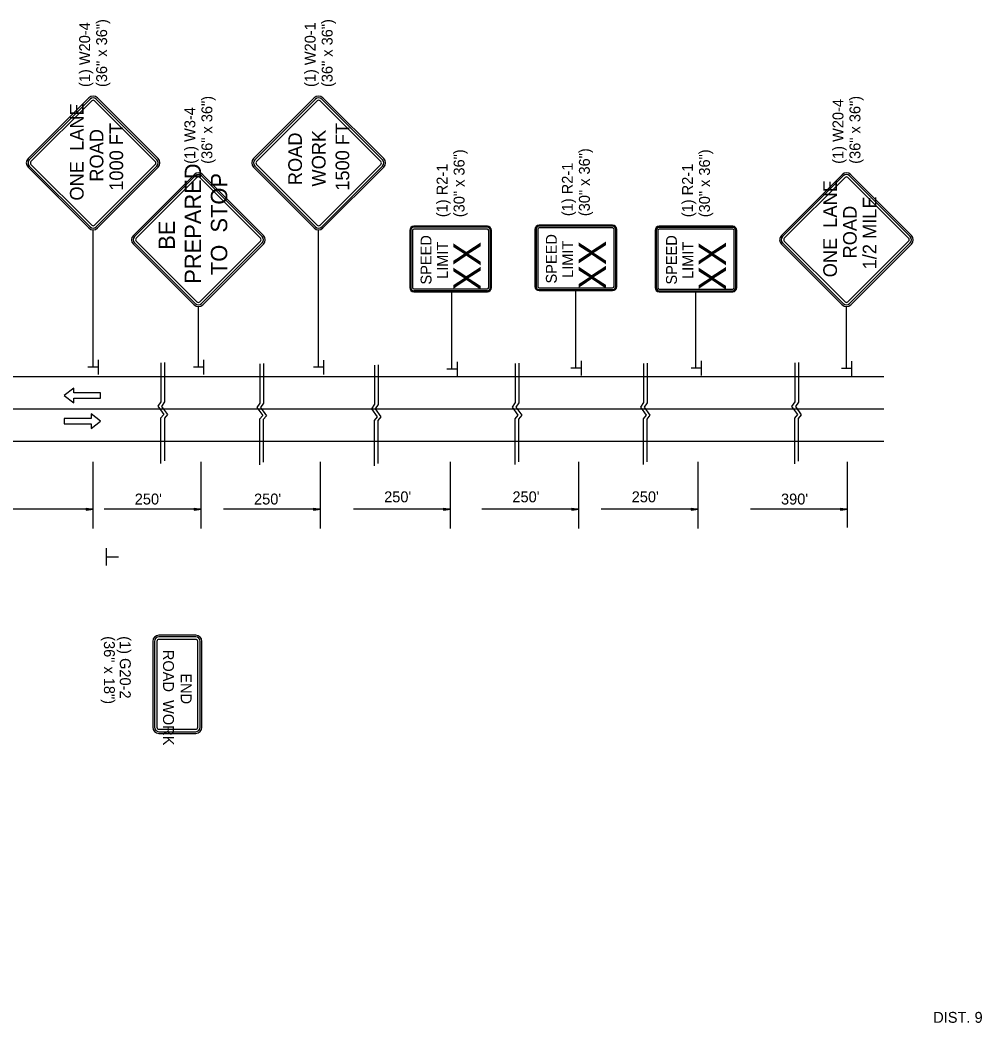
# Model space of a CAD drawing. Extents: x 1930579 to 1934718, y 596452 to 597844.
# Drawn here: x 1932620 to 1933150, y 596560 to 597112 of the extents above; entities that cross this region are included whole.
import ezdxf

# ---------------------------------------------------------------- set-up
doc = ezdxf.new("R2010")
doc.units = 0
for name, color, linetype in [('Default', 7, 'Continuous'), ('P_TC_Signs_Permanent', 7, 'Continuous'), ('P_TC_Signs_Temporary', 7, 'Continuous'), ('R_Annotation', 7, 'Continuous'), ('R_Striping', 7, 'Continuous')]:
    doc.layers.add(name, color=color, linetype=linetype)

msp = doc.modelspace()

# ---------------------------------------------------------------- linework, layer by layer
at = {"layer": 'Default'}
for p, q in [((1932663.23, 596924.51), (1932663.23, 596916.5)), ((1932721.33, 596924.51), (1932721.33, 596916.5)), ((1932787.34, 596924.41), (1932787.34, 596916.4)), ((1932860.88, 596923.37), (1932860.88, 596915.37)), ((1932929.09, 596923.95), (1932929.09, 596915.95)), ((1932995.19, 596923.9), (1932995.19, 596915.89)), ((1933078.02, 596923.73), (1933078.02, 596915.73)), ((1932663.11, 596920.53), (1932657.64, 596920.53)), ((1932721.21, 596920.53), (1932715.74, 596920.53)), ((1932787.22, 596920.43), (1932781.76, 596920.43)), ((1932860.76, 596919.39), (1932855.29, 596919.39)), ((1932928.98, 596919.97), (1932923.51, 596919.97)), ((1932995.08, 596919.92), (1932989.61, 596919.92)), ((1933077.9, 596919.75), (1933072.44, 596919.75)), ((1932378.86, 596915.33), (1932993.57, 596915.28)), ((1932993.57, 596915.28), (1933095.77, 596915.27)), ((1932378.14, 596897.54), (1933095.76, 596897.49)), ((1932378.64, 596879.75), (1932993.57, 596879.7)), ((1932993.57, 596879.7), (1933095.77, 596879.69)), ((1932660.61, 596831.69), (1932660.61, 596868.29)), ((1932720.06, 596831.69), (1932720.06, 596868.29)), ((1932785.71, 596831.69), (1932785.71, 596868.29)), ((1932857.31, 596831.69), (1932857.31, 596868.29)), ((1932927.92, 596831.69), (1932927.92, 596868.29)), ((1932993.57, 596831.69), (1932993.57, 596868.29)), ((1933075.76, 596832.26), (1933075.76, 596868.29)), ((1932660.61, 596842.28), (1932560.85, 596842.28)), ((1932656.77, 596842.85), (1932660.61, 596842.28)), ((1932656.77, 596842.85), (1932656.77, 596841.7)), ((1932656.77, 596842.76), (1932659.97, 596842.28)), ((1932656.77, 596842.66), (1932659.31, 596842.28)), ((1932656.77, 596842.56), (1932658.67, 596842.28)), ((1932656.77, 596842.46), (1932658.02, 596842.28)), ((1932656.77, 596842.37), (1932657.38, 596842.28)), ((1932656.77, 596841.7), (1932660.61, 596842.28)), ((1932656.77, 596842.09), (1932658.02, 596842.28)), ((1932656.77, 596841.89), (1932659.31, 596842.28)), ((1932656.77, 596841.8), (1932659.97, 596842.28)), ((1932656.77, 596841.99), (1932658.67, 596842.28)), ((1932656.77, 596842.19), (1932657.38, 596842.28)), ((1932720.06, 596842.28), (1932666.66, 596842.28)), ((1932716.22, 596842.85), (1932720.06, 596842.28)), ((1932716.22, 596842.85), (1932716.22, 596841.7)), ((1932716.22, 596842.76), (1932719.42, 596842.28)), ((1932716.22, 596842.66), (1932718.76, 596842.28)), ((1932716.22, 596842.56), (1932718.12, 596842.28)), ((1932716.22, 596842.46), (1932717.47, 596842.28)), ((1932716.22, 596842.37), (1932716.83, 596842.28)), ((1932716.22, 596841.7), (1932720.06, 596842.28)), ((1932716.22, 596842.09), (1932717.47, 596842.28)), ((1932716.22, 596841.89), (1932718.76, 596842.28)), ((1932716.22, 596841.8), (1932719.42, 596842.28)), ((1932716.22, 596841.99), (1932718.12, 596842.28)), ((1932716.22, 596842.19), (1932716.83, 596842.28)), ((1932785.71, 596842.28), (1932732.31, 596842.28)), ((1932781.88, 596842.85), (1932785.71, 596842.28)), ((1932781.88, 596842.85), (1932781.88, 596841.7)), ((1932781.88, 596842.76), (1932785.07, 596842.28)), ((1932781.88, 596842.66), (1932784.41, 596842.28)), ((1932781.88, 596842.56), (1932783.78, 596842.28)), ((1932781.88, 596842.46), (1932783.12, 596842.28)), ((1932781.88, 596842.37), (1932782.48, 596842.28)), ((1932781.88, 596841.7), (1932785.71, 596842.28)), ((1932781.88, 596842.09), (1932783.12, 596842.28)), ((1932781.88, 596841.89), (1932784.41, 596842.28)), ((1932781.88, 596841.8), (1932785.07, 596842.28)), ((1932781.88, 596841.99), (1932783.78, 596842.28)), ((1932781.88, 596842.19), (1932782.48, 596842.28)), ((1932857.31, 596842.28), (1932803.91, 596842.28)), ((1932853.47, 596842.85), (1932857.31, 596842.28)), ((1932853.47, 596842.85), (1932853.47, 596841.7)), ((1932853.47, 596842.76), (1932856.67, 596842.28)), ((1932853.47, 596842.66), (1932856.01, 596842.28)), ((1932853.47, 596842.56), (1932855.37, 596842.28)), ((1932853.47, 596842.46), (1932854.72, 596842.28)), ((1932853.47, 596842.37), (1932854.08, 596842.28)), ((1932853.47, 596841.7), (1932857.31, 596842.28)), ((1932853.47, 596842.09), (1932854.72, 596842.28)), ((1932853.47, 596841.89), (1932856.01, 596842.28)), ((1932853.47, 596841.8), (1932856.67, 596842.28)), ((1932853.47, 596841.99), (1932855.37, 596842.28)), ((1932853.47, 596842.19), (1932854.08, 596842.28)), ((1932927.92, 596842.28), (1932874.52, 596842.28)), ((1932924.08, 596842.85), (1932927.92, 596842.28)), ((1932924.08, 596842.85), (1932924.08, 596841.7)), ((1932924.08, 596842.76), (1932927.28, 596842.28)), ((1932924.08, 596842.66), (1932926.62, 596842.28)), ((1932924.08, 596842.56), (1932925.98, 596842.28)), ((1932924.08, 596842.46), (1932925.33, 596842.28)), ((1932924.08, 596842.37), (1932924.69, 596842.28)), ((1932924.08, 596841.7), (1932927.92, 596842.28)), ((1932924.08, 596842.09), (1932925.33, 596842.28)), ((1932924.08, 596841.89), (1932926.62, 596842.28)), ((1932924.08, 596841.8), (1932927.28, 596842.28)), ((1932924.08, 596841.99), (1932925.98, 596842.28)), ((1932924.08, 596842.19), (1932924.69, 596842.28)), ((1932993.57, 596842.28), (1932940.17, 596842.28)), ((1932989.73, 596842.85), (1932993.57, 596842.28)), ((1932989.73, 596842.85), (1932989.73, 596841.7)), ((1932989.73, 596842.76), (1932992.93, 596842.28)), ((1932989.73, 596842.66), (1932992.27, 596842.28)), ((1932989.73, 596842.56), (1932991.63, 596842.28)), ((1932989.73, 596842.46), (1932990.98, 596842.28)), ((1932989.73, 596842.37), (1932990.34, 596842.28)), ((1932989.73, 596841.7), (1932993.57, 596842.28)), ((1932989.73, 596842.09), (1932990.98, 596842.28)), ((1932989.73, 596841.89), (1932992.27, 596842.28)), ((1932989.73, 596841.8), (1932992.93, 596842.28)), ((1932989.73, 596841.99), (1932991.63, 596842.28)), ((1932989.73, 596842.19), (1932990.34, 596842.28)), ((1933075.76, 596842.28), (1933022.35, 596842.28)), ((1933071.92, 596842.85), (1933075.76, 596842.28)), ((1933071.92, 596842.85), (1933071.92, 596841.7)), ((1933071.92, 596842.76), (1933075.12, 596842.28)), ((1933071.92, 596842.66), (1933074.46, 596842.28)), ((1933071.92, 596842.56), (1933073.82, 596842.28)), ((1933071.92, 596842.46), (1933073.17, 596842.28)), ((1933071.92, 596842.37), (1933072.53, 596842.28)), ((1933071.92, 596841.7), (1933075.76, 596842.28)), ((1933071.92, 596842.09), (1933073.17, 596842.28)), ((1933071.92, 596841.89), (1933074.46, 596842.28)), ((1933071.92, 596841.8), (1933075.12, 596842.28)), ((1933071.92, 596841.99), (1933073.82, 596842.28)), ((1933071.92, 596842.19), (1933072.53, 596842.28)), ((1932667.87, 596811.37), (1932667.87, 596820.86)), ((1932668.01, 596816.09), (1932674.49, 596816.09))]:
    msp.add_line(p, q, dxfattribs=at)
for points in [[(1932697.84, 596922.91), (1932697.84, 596901.39), (1932696.18, 596898.92), (1932699.42, 596894.49), (1932697.71, 596892.44), (1932697.71, 596867.41)], [(1932699.89, 596923.11), (1932699.89, 596901.3), (1932698.23, 596898.83), (1932701.46, 596894.4), (1932699.76, 596892.36), (1932699.76, 596868.85)], [(1932754.35, 596922.46), (1932754.35, 596900.66), (1932752.69, 596898.18), (1932755.93, 596893.76), (1932754.22, 596891.71), (1932754.22, 596868.21)], [(1932892.79, 596922.48), (1932892.79, 596900.96), (1932891.13, 596898.49), (1932894.36, 596894.06), (1932892.66, 596892.01), (1932892.65, 596866.98)], [(1932894.83, 596922.67), (1932894.83, 596900.87), (1932893.17, 596898.4), (1932896.41, 596893.97), (1932894.7, 596891.92), (1932894.7, 596868.42)], [(1932963.4, 596922.48), (1932963.4, 596900.96), (1932961.73, 596898.49), (1932964.97, 596894.06), (1932963.27, 596892.01), (1932963.26, 596866.98)], [(1932965.44, 596922.67), (1932965.44, 596900.87), (1932963.78, 596898.4), (1932967.02, 596893.97), (1932965.31, 596891.92), (1932965.31, 596868.42)], [(1933046.67, 596922.82), (1933046.67, 596901.3), (1933045, 596898.83), (1933048.24, 596894.4), (1933046.54, 596892.35), (1933046.53, 596867.32)], [(1933048.71, 596923.02), (1933048.71, 596901.21), (1933047.05, 596898.74), (1933050.29, 596894.31), (1933048.58, 596892.27), (1933048.58, 596868.76)], [(1932752.31, 596922.26), (1932752.31, 596900.74), (1932750.64, 596898.27), (1932753.88, 596893.84), (1932752.18, 596891.8), (1932752.17, 596866.77)], [(1932815.35, 596921.59), (1932815.35, 596900.07), (1932813.68, 596897.6), (1932816.92, 596893.17), (1932815.22, 596891.12), (1932815.21, 596866.1)], [(1932817.39, 596921.79), (1932817.39, 596899.99), (1932815.73, 596897.51), (1932818.97, 596893.08), (1932817.26, 596891.04), (1932817.26, 596867.54)]]:
    msp.add_lwpolyline(points, dxfattribs=at)
at = {"layer": 'P_TC_Signs_Permanent'}
for p, q in [((1932716.09, 597026.42), (1932682.68, 596993.01)), ((1932716.75, 597025.75), (1932683.34, 596992.34)), ((1932717.68, 597024.82), (1932684.27, 596991.41)), ((1932752.68, 596991.41), (1932719.27, 597024.82)), ((1932753.61, 596992.34), (1932720.2, 597025.75)), ((1932754.27, 596993.01), (1932720.86, 597026.42)), ((1932834.78, 596995.76), (1932834.78, 596964.26)), ((1932835.34, 596995.76), (1932835.34, 596964.26)), ((1932836.28, 596995.76), (1932836.28, 596964.26)), ((1932877.53, 596998.01), (1932837.03, 596998.01)), ((1932877.53, 596997.45), (1932837.03, 596997.45)), ((1932877.53, 596996.51), (1932837.03, 596996.51)), ((1932878.28, 596964.26), (1932878.28, 596995.76)), ((1932879.21, 596964.26), (1932879.21, 596995.76)), ((1932879.78, 596964.26), (1932879.78, 596995.76)), ((1932903.74, 596996.34), (1932903.74, 596964.84)), ((1932904.31, 596996.34), (1932904.31, 596964.84)), ((1932905.24, 596996.34), (1932905.24, 596964.84)), ((1932946.49, 596998.59), (1932905.99, 596998.59)), ((1932946.49, 596998.03), (1932905.99, 596998.03)), ((1932946.49, 596997.09), (1932905.99, 596997.09)), ((1932947.24, 596964.84), (1932947.24, 596996.34)), ((1932948.18, 596964.84), (1932948.18, 596996.34)), ((1932948.74, 596964.84), (1932948.74, 596996.34)), ((1932969.85, 596995.74), (1932969.85, 596964.24)), ((1932970.41, 596995.74), (1932970.41, 596964.24)), ((1932971.35, 596995.74), (1932971.35, 596964.24)), ((1933012.6, 596997.99), (1932972.1, 596997.99)), ((1933012.6, 596997.43), (1932972.1, 596997.43)), ((1933012.6, 596996.49), (1932972.1, 596996.49)), ((1933013.35, 596964.24), (1933013.35, 596995.74)), ((1933014.28, 596964.24), (1933014.28, 596995.74)), ((1933014.85, 596964.24), (1933014.85, 596995.74)), ((1932683.34, 596988.89), (1932716.75, 596955.48)), ((1932684.27, 596989.82), (1932717.68, 596956.41)), ((1932719.27, 596956.41), (1932752.68, 596989.82)), ((1932720.2, 596955.48), (1932753.61, 596988.89)), ((1932682.68, 596988.23), (1932716.09, 596954.82)), ((1932720.86, 596954.82), (1932754.27, 596988.23)), ((1932837.03, 596963.51), (1932877.53, 596963.51)), ((1932837.03, 596962.58), (1932877.53, 596962.58)), ((1932837.03, 596962.01), (1932877.53, 596962.01)), ((1932905.99, 596964.09), (1932946.49, 596964.09)), ((1932905.99, 596963.16), (1932946.49, 596963.16)), ((1932905.99, 596962.59), (1932946.49, 596962.59)), ((1932972.1, 596963.49), (1933012.6, 596963.49)), ((1932972.1, 596962.55), (1933012.6, 596962.55)), ((1932972.1, 596961.99), (1933012.6, 596961.99))]:
    msp.add_line(p, q, dxfattribs=at)
for centre, radius, start, end in [((1932718.48, 597024.03), 3.38, 45, 135), ((1932718.48, 597024.03), 2.44, 45, 135), ((1932718.48, 597024.03), 1.13, 45, 135), ((1932837.03, 596995.76), 2.25, 90, 180), ((1932837.03, 596995.76), 1.69, 90, 180), ((1932837.03, 596995.76), 0.75, 90, 180), ((1932877.53, 596995.76), 2.25, 360, 90), ((1932877.53, 596995.76), 1.69, 360, 90), ((1932877.53, 596995.76), 0.75, 360, 90), ((1932905.99, 596996.34), 2.25, 90, 180), ((1932905.99, 596996.34), 1.69, 90, 180), ((1932905.99, 596996.34), 0.75, 90, 180), ((1932946.49, 596996.34), 2.25, 360, 90), ((1932946.49, 596996.34), 1.69, 360, 90), ((1932946.49, 596996.34), 0.75, 360, 90), ((1932972.1, 596995.74), 2.25, 90, 180), ((1932972.1, 596995.74), 1.69, 90, 180), ((1932972.1, 596995.74), 0.75, 90, 180), ((1933012.6, 596995.74), 2.25, 360, 90), ((1933012.6, 596995.74), 1.69, 360, 90), ((1933012.6, 596995.74), 0.75, 360, 90), ((1932685.07, 596990.62), 3.38, 135, 225), ((1932685.07, 596990.62), 2.44, 135, 225), ((1932685.07, 596990.62), 1.13, 135, 225), ((1932751.89, 596990.62), 1.13, 315, 45), ((1932751.89, 596990.62), 2.44, 315, 45), ((1932751.89, 596990.62), 3.38, 315, 45), ((1932837.03, 596964.26), 2.25, 180, 270), ((1932837.03, 596964.26), 1.69, 180, 270), ((1932837.03, 596964.26), 0.75, 180, 270), ((1932877.53, 596964.26), 2.25, 270, 360), ((1932877.53, 596964.26), 1.69, 270, 360), ((1932877.53, 596964.26), 0.75, 270, 360), ((1932905.99, 596964.84), 2.25, 180, 270), ((1932905.99, 596964.84), 1.69, 180, 270), ((1932905.99, 596964.84), 0.75, 180, 270), ((1932946.49, 596964.84), 2.25, 270, 360), ((1932946.49, 596964.84), 1.69, 270, 360), ((1932946.49, 596964.84), 0.75, 270, 360), ((1932972.1, 596964.24), 2.25, 180, 270), ((1932972.1, 596964.24), 1.69, 180, 270), ((1932972.1, 596964.24), 0.75, 180, 270), ((1933012.6, 596964.24), 2.25, 270, 360), ((1933012.6, 596964.24), 1.69, 270, 360), ((1933012.6, 596964.24), 0.75, 270, 360), ((1932718.48, 596957.21), 1.13, 225, 315), ((1932718.48, 596957.21), 3.38, 225, 315), ((1932718.48, 596957.21), 2.44, 225, 315)]:
    msp.add_arc(centre, radius, start, end, dxfattribs=at)
at = {"layer": 'P_TC_Signs_Temporary'}
for p, q in [((1932624.75, 597035.26), (1932658.16, 597068.67)), ((1932625.41, 597034.6), (1932658.83, 597068.01)), ((1932626.34, 597033.67), (1932659.75, 597067.08)), ((1932661.34, 597067.08), (1932694.76, 597033.67)), ((1932662.27, 597068.01), (1932695.68, 597034.6)), ((1932662.94, 597068.67), (1932696.35, 597035.26)), ((1932748.86, 597035.26), (1932782.28, 597068.67)), ((1932749.53, 597034.6), (1932782.94, 597068.01)), ((1932750.46, 597033.67), (1932783.87, 597067.08)), ((1932785.46, 597067.08), (1932818.87, 597033.67)), ((1932786.39, 597068.01), (1932819.8, 597034.6)), ((1932787.05, 597068.67), (1932820.46, 597035.26)), ((1932658.16, 596997.07), (1932624.75, 597030.49)), ((1932658.83, 596997.74), (1932625.41, 597031.15)), ((1932659.75, 596998.67), (1932626.34, 597032.08)), ((1932694.76, 597032.08), (1932661.34, 596998.67)), ((1932695.68, 597031.15), (1932662.27, 596997.74)), ((1932696.35, 597030.49), (1932662.94, 596997.07)), ((1932782.28, 596997.07), (1932748.86, 597030.49)), ((1932782.94, 596997.74), (1932749.53, 597031.15)), ((1932783.87, 596998.67), (1932750.46, 597032.08)), ((1932818.87, 597032.08), (1932785.46, 596998.67)), ((1932819.8, 597031.15), (1932786.39, 596997.74)), ((1932820.46, 597030.49), (1932787.05, 596997.07)), ((1933039.37, 596993.01), (1933072.78, 597026.42)), ((1933040.04, 596992.34), (1933073.45, 597025.75)), ((1933040.96, 596991.41), (1933074.37, 597024.82)), ((1933075.96, 597024.82), (1933109.38, 596991.41)), ((1933076.89, 597025.75), (1933110.3, 596992.34)), ((1933077.56, 597026.42), (1933110.97, 596993.01)), ((1933073.45, 596955.48), (1933040.04, 596988.89)), ((1933074.37, 596956.41), (1933040.96, 596989.82)), ((1933109.38, 596989.82), (1933075.96, 596956.41)), ((1933110.3, 596988.89), (1933076.89, 596955.48)), ((1933072.78, 596954.82), (1933039.37, 596988.23)), ((1933110.97, 596988.23), (1933077.56, 596954.82)), ((1932693.39, 596769.54), (1932693.39, 596722.29)), ((1932694.33, 596769.54), (1932694.33, 596722.29)), ((1932695.64, 596769.54), (1932695.64, 596722.29)), ((1932717.02, 596772.92), (1932696.77, 596772.92)), ((1932717.02, 596771.98), (1932696.77, 596771.98)), ((1932717.02, 596770.67), (1932696.77, 596770.67)), ((1932718.14, 596722.29), (1932718.14, 596769.54)), ((1932719.45, 596722.29), (1932719.45, 596769.54)), ((1932720.39, 596722.29), (1932720.39, 596769.54)), ((1932696.77, 596721.17), (1932717.02, 596721.17)), ((1932696.77, 596719.85), (1932717.02, 596719.85)), ((1932696.77, 596718.92), (1932717.02, 596718.92))]:
    msp.add_line(p, q, dxfattribs=at)
for centre, radius, start, end in [((1932660.55, 597066.28), 3.38, 45, 135), ((1932660.55, 597066.28), 2.44, 45, 135), ((1932660.55, 597066.28), 1.12, 45, 135), ((1932784.66, 597066.28), 3.38, 45, 135), ((1932784.66, 597066.28), 2.44, 45, 135), ((1932784.66, 597066.28), 1.12, 45, 135), ((1932627.14, 597032.87), 3.38, 135, 225), ((1932627.14, 597032.87), 2.44, 135, 225), ((1932627.14, 597032.87), 1.13, 135, 225), ((1932693.96, 597032.87), 1.13, 315, 45), ((1932693.96, 597032.87), 2.44, 315, 45), ((1932693.96, 597032.87), 3.38, 315, 45), ((1932751.25, 597032.87), 3.38, 135, 225), ((1932751.25, 597032.87), 2.44, 135, 225), ((1932751.25, 597032.87), 1.13, 135, 225), ((1932818.07, 597032.87), 1.13, 315, 45), ((1932818.07, 597032.87), 2.44, 315, 45), ((1932818.07, 597032.87), 3.38, 315, 45), ((1933075.17, 597024.03), 3.38, 45, 135), ((1933075.17, 597024.03), 2.44, 45, 135), ((1933075.17, 597024.03), 1.12, 45, 135), ((1932660.55, 596999.46), 3.38, 225, 315), ((1932660.55, 596999.46), 2.44, 225, 315), ((1932660.55, 596999.46), 1.12, 225, 315), ((1932784.66, 596999.46), 3.38, 225, 315), ((1932784.66, 596999.46), 2.44, 225, 315), ((1932784.66, 596999.46), 1.12, 225, 315), ((1933041.76, 596990.62), 3.38, 135, 225), ((1933041.76, 596990.62), 2.44, 135, 225), ((1933041.76, 596990.62), 1.13, 135, 225), ((1933108.58, 596990.62), 1.13, 315, 45), ((1933108.58, 596990.62), 2.44, 315, 45), ((1933108.58, 596990.62), 3.38, 315, 45), ((1933075.17, 596957.21), 1.12, 225, 315), ((1933075.17, 596957.21), 3.38, 225, 315), ((1933075.17, 596957.21), 2.44, 225, 315), ((1932696.77, 596769.54), 3.38, 90, 180), ((1932696.77, 596769.54), 2.44, 90, 180), ((1932696.77, 596769.54), 1.13, 90, 180), ((1932717.02, 596769.54), 3.38, 360, 90), ((1932717.02, 596769.54), 2.44, 360, 90), ((1932717.02, 596769.54), 1.13, 360, 90), ((1932696.77, 596722.29), 3.38, 180, 270), ((1932696.77, 596722.29), 2.44, 180, 270), ((1932696.77, 596722.29), 1.13, 180, 270), ((1932717.02, 596722.29), 2.44, 270, 360), ((1932717.02, 596722.29), 1.13, 270, 360), ((1932717.02, 596722.29), 3.38, 270, 360)]:
    msp.add_arc(centre, radius, start, end, dxfattribs=at)
at = {"layer": 'R_Annotation'}
for p, q in [((1932660.55, 596920.53), (1932660.55, 596996.09)), ((1932784.66, 596920.43), (1932784.66, 596996.09)), ((1932858.03, 596919.39), (1932858.03, 596962.01)), ((1932926.24, 596919.97), (1932926.24, 596962.59)), ((1932992.34, 596919.92), (1932992.34, 596961.99)), ((1932718.48, 596920.53), (1932718.48, 596953.83)), ((1933075.17, 596919.75), (1933075.17, 596953.83))]:
    msp.add_line(p, q, dxfattribs=at)
at = {"layer": 'R_Striping'}
for points in [[(1932649.88, 596908.84), (1932644.69, 596904.84), (1932649.88, 596900.84), (1932649.88, 596903.34), (1932664.59, 596903.34), (1932664.59, 596906.34), (1932649.88, 596906.34)], [(1932659.4, 596886.7), (1932664.59, 596890.7), (1932659.4, 596894.7), (1932659.4, 596892.2), (1932644.69, 596892.2), (1932644.69, 596889.2), (1932659.4, 596889.2)]]:
    msp.add_lwpolyline(points, close=True, dxfattribs=at)

# ---------------------------------------------------------------- texts
at = {"layer": 'Default'}
for s, p in [("250'", (1932683.46, 596844.88)), ("250'", (1932749.11, 596844.88)), ("250'", (1932820.71, 596846.1)), ("250'", (1932891.32, 596846.1)), ("250'", (1932956.97, 596846.1)), ("390'", (1933039.15, 596844.88))]:
    msp.add_text(s, height=6, rotation=360, dxfattribs=at).set_placement(p)
at = {"layer": 'P_TC_Signs_Permanent'}
for s, height, p in [('SPEED', 6, (1932846.78, 596965.94)), ('LIMIT', 6, (1932855.78, 596969.03)), ('XX', 15, (1932873.78, 596962.71)), ('SPEED', 6, (1932915.74, 596966.52)), ('LIMIT', 6, (1932924.74, 596969.61)), ('XX', 15, (1932942.74, 596963.29)), ('SPEED', 6, (1932981.85, 596965.92)), ('LIMIT', 6, (1932990.85, 596969.01)), ('XX', 15, (1933008.85, 596962.69))]:
    msp.add_text(s, height=height, rotation=90, dxfattribs=at).set_placement(p)
at = {"layer": 'P_TC_Signs_Temporary'}
for s, height, rotation, p in [('ONE  LANE', 7.5, 90, (1932655.3, 597012.17)), ('ROAD', 7.5, 90, (1932666.17, 597022.57)), ('1000 FT', 7.5, 90, (1932677.05, 597017.58)), ('WORK', 7.5, 90, (1932788.47, 597019.88)), ('1500 FT', 7.5, 90, (1932801.5, 597017.58)), (' ROAD ', 7.5, 90, (1932775.45, 597017.85)), ('PREPARED', 9, 90, (1932719.95, 596966.38)), ('TO  STOP', 9, 90, (1932734.35, 596971.15)), ('ONE  LANE', 7.5, 90, (1933069.92, 596969.92)), ('1/2 MILE', 7.5, 90, (1933091.67, 596974.3)), ('ROAD', 7.5, 90, (1933080.79, 596980.31)), ('BE', 9, 90, (1932705.55, 596985.07)), ('ROAD  WORK', 6, 270, (1932699.02, 596764.88)), ('END', 6, 270, (1932708.77, 596751.95))]:
    msp.add_text(s, height=height, rotation=rotation, dxfattribs=at).set_placement(p)
at = {"layer": 'R_Annotation'}
for s, height, rotation, p in [('(1) W20-4', 6, 90, (1932658.87, 597074.66)), ('(36" x 36")', 5.9996, 90, (1932668.23, 597074.66)), ('(36" x 36")', 5.9996, 90, (1932792.34, 597074.66)), ('(1) W20-1', 6, 90, (1932782.98, 597074.66)), ('(36" x 36")', 5.9996, 90, (1932726.16, 597032.4)), ('(1) W20-4', 6, 90, (1933073.49, 597032.4)), ('(36" x 36")', 6, 90, (1933082.85, 597032.4)), ('(1) W3-4', 6, 90, (1932716.79, 597032.4)), ('(30" x 36")', 5.9996, 90, (1932864.96, 597003.01)), ('(30" x 36")', 5.9996, 90, (1932933.93, 597003.59)), ('(30" x 36")', 5.9996, 90, (1933000.03, 597002.99)), ('(1) R2-1', 6, 90, (1932855.59, 597003.01)), ('(1) R2-1', 6, 90, (1932924.56, 597003.59)), ('(1) R2-1', 6, 90, (1932990.66, 597002.99)), ('(36" x 18")', 5.9996, 270, (1932666.49, 596772.4)), ('(1) G20-2', 6, 270, (1932675.24, 596772.4)), ('DIST. 9', 6, 360, (1933122.93, 596559.62))]:
    msp.add_text(s, height=height, rotation=rotation, dxfattribs=at).set_placement(p)

doc.saveas('drawing.dxf')
